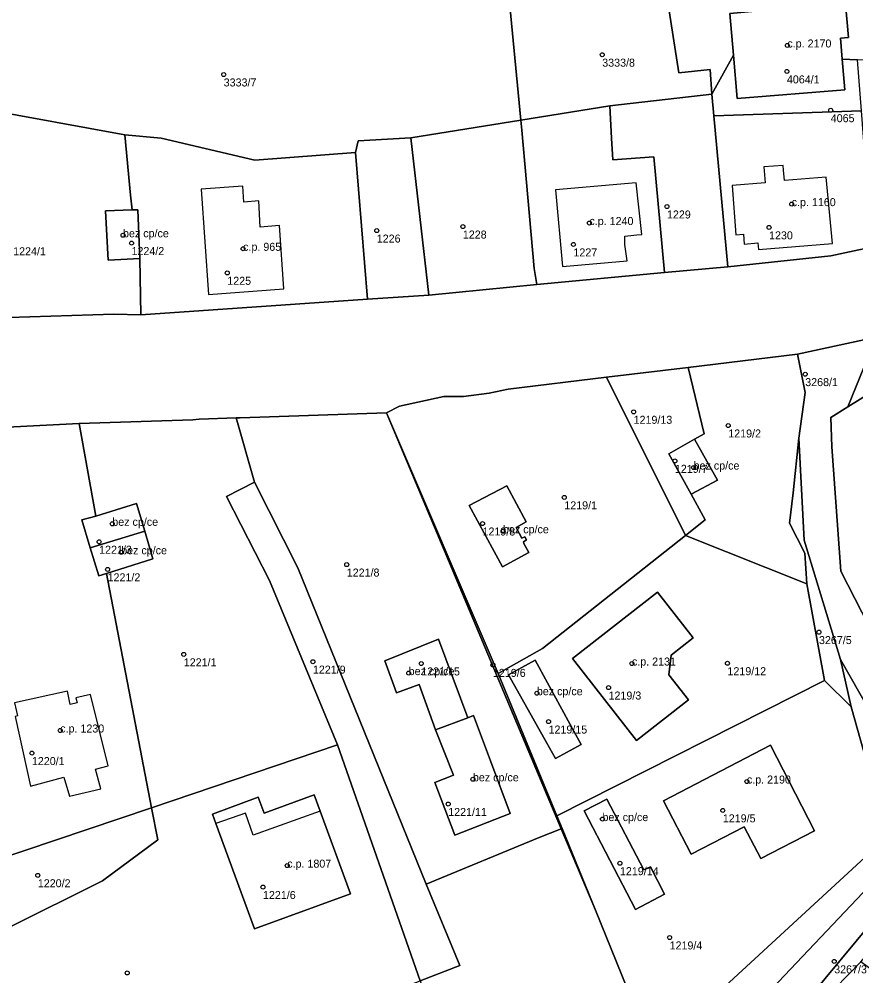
# Model space of a CAD drawing. Extents: x -878211 to -870363, y -1058464 to -1052522.
# Drawn here: x -875754.6 to -875650, y -1056338.1 to -1056218.5 of the extents above; entities that cross this region are included whole.
import ezdxf

# ---------------------------------------------------------------- set-up
doc = ezdxf.new("R2010")
doc.units = 0
for name, color, linetype in [('Vrstva 50', 7, 'Continuous'), ('Vrstva 51', 7, 'Continuous'), ('Vrstva 52', 7, 'Continuous')]:
    doc.layers.add(name, color=color, linetype=linetype)

msp = doc.modelspace()

# ---------------------------------------------------------------- linework, layer by layer
at = {"layer": 'Vrstva 50'}
for centre in [(-875658.59, -1056221.79994), (-875681.73, -1056222.95994), (-875729.04, -1056225.42994), (-875658.65, -1056225.04994), (-875653.17, -1056229.89994), (-875658.05, -1056241.62994), (-875673.64, -1056241.92994), (-875683.33, -1056243.98994), (-875709.91, -1056244.93994), (-875699.15, -1056244.43994), (-875660.88, -1056244.53994), (-875741.62, -1056245.51994), (-875740.56, -1056246.49994), (-875726.61, -1056247.20994), (-875685.33, -1056246.66994), (-875728.59, -1056250.21994), (-875656.36, -1056262.87994), (-875677.81, -1056267.58994), (-875665.98, -1056269.29994), (-875672.65, -1056273.71994), (-875670.31, -1056274.54994), (-875686.47, -1056278.27994), (-875742.96, -1056281.57994), (-875696.69, -1056281.54994), (-875694.13, -1056282.50994), (-875744.61, -1056283.82994), (-875741.85, -1056285.13994), (-875713.66, -1056286.67994), (-875743.55, -1056287.27994), (-875654.64, -1056295.11994), (-875734.03, -1056297.89994), (-875717.89, -1056298.80994), (-875666.08, -1056299.00994), (-875704.35, -1056299.03994), (-875695.39, -1056299.21994), (-875678.02, -1056299.03994), (-875705.92, -1056300.23994), (-875680.94, -1056302.04994), (-875689.9, -1056302.74994), (-875688.44, -1056306.29994), (-875749.47, -1056307.40994), (-875753.01, -1056310.23994), (-875697.89, -1056313.50994), (-875663.65, -1056313.78994), (-875700.98, -1056316.59994), (-875666.66, -1056317.39994), (-875681.7, -1056318.47994), (-875679.52, -1056323.99994), (-875721.1, -1056324.29994), (-875752.27, -1056325.50994), (-875724.13, -1056326.97994), (-875673.31, -1056333.27994), (-875652.74, -1056336.26994), (-875741.1, -1056337.70994)]:
    msp.add_circle(centre, 0.25, dxfattribs=at)
at = {"layer": 'Vrstva 51'}
for points in [[(-875725.16, -1056236.15), (-875712.56, -1056235.19), (-875712.23, -1056233.71), (-875705.64, -1056233.36), (-875691.89, -1056231.13), (-875693.69, -1056212.47), (-875696.36, -1056212.7), (-875722.48, -1056215.76), (-875734.27, -1056214.88), (-875746.69, -1056208.31), (-875753.19, -1056192.84), (-875758.13, -1056177.67), (-875755.87, -1056195.65), (-875753.15, -1056204.3), (-875763.53, -1056214.45), (-875759.23, -1056229.71), (-875741.39, -1056232.96), (-875736.87, -1056233.37)], [(-875691.89, -1056231.13), (-875680.79, -1056229.33), (-875668.04, -1056227.87), (-875668.25, -1056224.81), (-875672.16, -1056225.23), (-875674.08, -1056212.9), (-875665.21, -1056213.09), (-875654.49, -1056214.36), (-875647.13, -1056215.85), (-875654.87, -1056210.56), (-875687.08, -1056211.89), (-875693.69, -1056212.47)], [(-875665.21, -1056213.09), (-875674.08, -1056212.9), (-875672.16, -1056225.23), (-875668.25, -1056224.81), (-875668.04, -1056227.87), (-875665.34, -1056222.99), (-875665.77, -1056217.8), (-875660.26, -1056217.32), (-875660.37, -1056216.1), (-875654.42, -1056215.61), (-875654.32, -1056216.83), (-875651.32, -1056216.58), (-875650.95, -1056220.79), (-875651.94, -1056220.88), (-875651.73, -1056223.53), (-875649.81, -1056223.61), (-875636.91, -1056223.14), (-875647.13, -1056215.85), (-875654.49, -1056214.36)], [(-875665.34, -1056222.99), (-875664.88, -1056228.42), (-875651.43, -1056227.33), (-875651.73, -1056223.53), (-875651.94, -1056220.88), (-875650.95, -1056220.79), (-875651.32, -1056216.58), (-875654.32, -1056216.83), (-875654.42, -1056215.61), (-875660.37, -1056216.1), (-875660.26, -1056217.32), (-875665.77, -1056217.8)], [(-875665.34, -1056222.99), (-875668.04, -1056227.87), (-875667.79, -1056230.61), (-875649.32, -1056229.95), (-875649.81, -1056223.61), (-875651.73, -1056223.53), (-875651.43, -1056227.33), (-875664.88, -1056228.42)], [(-875668.04, -1056227.87), (-875680.79, -1056229.33), (-875680.56, -1056233.39), (-875680.41, -1056236.11), (-875675.27, -1056235.7), (-875673.94, -1056250.18), (-875666.04, -1056249.45), (-875667.79, -1056230.61)], [(-875680.79, -1056229.33), (-875691.89, -1056231.13), (-875691.78, -1056232.37), (-875690.23, -1056249.66), (-875689.91, -1056251.66), (-875673.94, -1056250.18), (-875675.27, -1056235.7), (-875680.41, -1056236.11), (-875680.56, -1056233.39)], [(-875741.39, -1056232.96), (-875759.23, -1056229.71), (-875758.54, -1056255.86), (-875742.77, -1056255.38), (-875739.4, -1056255.45), (-875739.51, -1056248.42), (-875743.48, -1056248.63), (-875743.8, -1056242.47), (-875740.49, -1056242.35), (-875740.67, -1056240.5)], [(-875645.38, -1056246.43), (-875646.3, -1056237.25), (-875647.81, -1056237.69), (-875648.81, -1056236.55), (-875649.32, -1056229.95), (-875667.79, -1056230.61), (-875666.04, -1056249.45), (-875653.18, -1056248.09)], [(-875691.89, -1056231.13), (-875705.64, -1056233.36), (-875703.39, -1056253.02), (-875689.91, -1056251.66), (-875690.23, -1056249.66), (-875691.78, -1056232.37)], [(-875739.51, -1056248.42), (-875739.4, -1056255.45), (-875711.05, -1056253.52), (-875712.56, -1056235.19), (-875725.16, -1056236.15), (-875736.87, -1056233.37), (-875741.39, -1056232.96), (-875740.67, -1056240.5), (-875740.49, -1056242.35), (-875739.77, -1056242.32)], [(-875712.56, -1056235.19), (-875711.05, -1056253.52), (-875703.39, -1056253.02), (-875705.64, -1056233.36), (-875712.23, -1056233.71)], [(-875739.51, -1056248.42), (-875739.77, -1056242.32), (-875740.49, -1056242.35), (-875743.8, -1056242.47), (-875743.48, -1056248.63)], [(-875647.49, -1056258.27), (-875651.02, -1056266.97), (-875633.44, -1056256.06), (-875633.64, -1056255.3)], [(-875633.44, -1056256.06), (-875651.02, -1056266.97), (-875653.18, -1056268.31), (-875653.03, -1056271.94), (-875651.92, -1056287.51), (-875643.13, -1056304.67), (-875633.03, -1056304.67), (-875621.48, -1056302.6), (-875626.03, -1056285.45), (-875627.65, -1056278.13)], [(-875657.32, -1056260.37), (-875670.99, -1056262.03), (-875669, -1056270.33), (-875670.18, -1056271.02), (-875667.34, -1056276.11), (-875670.61, -1056277.89), (-875668.86, -1056281.08), (-875671.33, -1056283.03), (-875656.16, -1056289.1), (-875656.42, -1056285.26), (-875658.32, -1056281.49), (-875657.87, -1056277.71), (-875657.17, -1056270.86), (-875656.36, -1056265.18)], [(-875681.21, -1056263.26), (-875671.33, -1056283.03), (-875668.86, -1056281.08), (-875670.61, -1056277.89), (-875673.39, -1056272.84), (-875670.18, -1056271.02), (-875669, -1056270.33), (-875670.99, -1056262.03)], [(-875681.21, -1056263.26), (-875693.47, -1056264.74), (-875695.88, -1056265.24), (-875699.05, -1056265.68), (-875701.53, -1056265.67), (-875707.05, -1056266.86), (-875708.7, -1056267.72), (-875694.72, -1056300.28), (-875689.19, -1056297.18), (-875671.33, -1056283.03)], [(-875732.09, -1056268.5), (-875732.89, -1056268.59), (-875747.11, -1056269.04), (-875745.02, -1056280.63), (-875739.93, -1056279.05), (-875738.91, -1056282.5), (-875737.88, -1056285.94), (-875743.68, -1056287.79), (-875738.05, -1056317.07), (-875714.83, -1056309.2), (-875723.33, -1056288.66), (-875728.69, -1056278.17), (-875725.2, -1056276.37), (-875727.49, -1056268.34)], [(-875686.86, -1056319.7), (-875708.7, -1056267.72), (-875726.98, -1056268.32), (-875727.49, -1056268.34), (-875725.2, -1056276.37), (-875719.78, -1056287.09), (-875703.74, -1056326.61), (-875689.62, -1056320.79)], [(-875686.86, -1056319.7), (-875682.59, -1056329.88), (-875686.75, -1056319.66), (-875687.42, -1056318.06), (-875694.72, -1056300.28), (-875708.7, -1056267.72)], [(-875768.46, -1056271.25), (-875776.25, -1056272.71), (-875771.36, -1056309.08), (-875769.67, -1056318.12), (-875763.34, -1056337.52), (-875757.22, -1056335.33), (-875756.47, -1056331.18), (-875758.02, -1056323.76), (-875738.05, -1056317.07), (-875743.68, -1056287.79), (-875744.66, -1056288.1), (-875745.71, -1056284.6), (-875746.76, -1056281.09), (-875745.02, -1056280.63), (-875747.11, -1056269.04), (-875761.01, -1056269.76)], [(-875670.61, -1056277.89), (-875667.34, -1056276.11), (-875670.18, -1056271.02), (-875673.39, -1056272.84)], [(-875656.16, -1056289.1), (-875653.97, -1056301.14), (-875650.62, -1056304.44), (-875651.97, -1056298.54), (-875656.48, -1056283.62), (-875657.17, -1056270.86), (-875657.87, -1056277.71), (-875658.32, -1056281.49), (-875656.42, -1056285.26)], [(-875725.2, -1056276.37), (-875728.69, -1056278.17), (-875723.33, -1056288.66), (-875714.83, -1056309.2), (-875704.48, -1056338.69), (-875699.54, -1056336.78), (-875703.74, -1056326.61), (-875719.78, -1056287.09)], [(-875691.59, -1056283.84), (-875691.18, -1056283.6), (-875691.42, -1056283.21), (-875691.76, -1056283.39), (-875692.5, -1056282.03), (-875691.22, -1056281.32), (-875693.64, -1056276.82), (-875698.34, -1056279.3), (-875694.21, -1056286.96), (-875690.9, -1056285.18), (-875691.52, -1056284.02)], [(-875691.59, -1056283.84), (-875691.52, -1056284.02), (-875690.9, -1056285.18), (-875694.21, -1056286.96), (-875698.34, -1056279.3), (-875693.64, -1056276.82), (-875691.22, -1056281.32), (-875692.5, -1056282.03), (-875691.76, -1056283.39), (-875691.42, -1056283.21), (-875691.18, -1056283.6)], [(-875738.91, -1056282.5), (-875739.93, -1056279.05), (-875745.02, -1056280.63), (-875746.76, -1056281.09), (-875745.71, -1056284.6)], [(-875744.66, -1056288.1), (-875743.68, -1056287.79), (-875737.88, -1056285.94), (-875738.91, -1056282.5), (-875745.71, -1056284.6)], [(-875671.33, -1056283.03), (-875689.19, -1056297.18), (-875694.72, -1056300.28), (-875687.42, -1056318.06), (-875653.97, -1056301.14), (-875656.16, -1056289.1)], [(-875677.46, -1056308.66), (-875685.45, -1056298.43), (-875674.83, -1056290.13), (-875670.37, -1056295.84), (-875673.12, -1056297.99), (-875673.42, -1056300.45), (-875670.96, -1056303.59)], [(-875677.46, -1056308.66), (-875670.96, -1056303.59), (-875673.42, -1056300.45), (-875673.12, -1056297.99), (-875670.37, -1056295.84), (-875674.83, -1056290.13), (-875685.45, -1056298.43)], [(-875698.51, -1056305.81), (-875702.18, -1056296), (-875708.92, -1056298.71), (-875707.43, -1056302.7), (-875704.6, -1056301.64), (-875702.56, -1056307.33)], [(-875698.51, -1056305.81), (-875697.8, -1056305.54), (-875695.68, -1056311.19), (-875693.22, -1056317.77), (-875700.15, -1056320.48), (-875702.66, -1056313.91), (-875700.31, -1056313.01), (-875702.56, -1056307.33), (-875704.6, -1056301.64), (-875707.43, -1056302.7), (-875708.92, -1056298.71), (-875702.18, -1056296)], [(-875642.54, -1056321.47), (-875642.63, -1056314.95), (-875651.97, -1056298.54), (-875650.62, -1056304.44), (-875646.62, -1056318.65), (-875647.82, -1056322.26), (-875646.14, -1056324.55), (-875663.43, -1056342.76), (-875673.95, -1056351.87), (-875694.33, -1056369.52), (-875703.32, -1056374.74), (-875703.43, -1056377.18), (-875695.25, -1056372.67), (-875703.53, -1056381.51), (-875697.87, -1056377.14), (-875677.29, -1056358.5), (-875662.3, -1056346.67), (-875657.54, -1056342.8), (-875646.31, -1056329.33)], [(-875693.43, -1056300.46), (-875690.12, -1056298.6), (-875685.47, -1056307.11), (-875684.37, -1056309.14), (-875687.59, -1056310.9), (-875688.69, -1056308.91)], [(-875693.43, -1056300.46), (-875688.69, -1056308.91), (-875687.59, -1056310.9), (-875684.37, -1056309.14), (-875685.47, -1056307.11), (-875690.12, -1056298.6)], [(-875675.36, -1056347.63), (-875647.82, -1056322.26), (-875646.62, -1056318.65), (-875650.62, -1056304.44), (-875653.97, -1056301.14), (-875687.42, -1056318.06), (-875686.75, -1056319.66), (-875682.59, -1056329.88)], [(-875698.51, -1056305.81), (-875702.56, -1056307.33), (-875700.31, -1056313.01), (-875702.66, -1056313.91), (-875700.15, -1056320.48), (-875693.22, -1056317.77), (-875695.68, -1056311.19), (-875697.8, -1056305.54)], [(-875704.48, -1056338.69), (-875714.83, -1056309.2), (-875738.05, -1056317.07), (-875737.28, -1056321.06), (-875744.17, -1056326.18), (-875756.07, -1056332.11), (-875757.22, -1056335.33), (-875755.32, -1056341.37), (-875750.57, -1056356.47)], [(-875674.07, -1056316.18), (-875660.72, -1056309.23), (-875655.21, -1056319.96), (-875661.89, -1056323.4), (-875663.99, -1056319.43), (-875670.62, -1056322.88)], [(-875674.07, -1056316.18), (-875670.62, -1056322.88), (-875663.99, -1056319.43), (-875661.89, -1056323.4), (-875655.21, -1056319.96), (-875660.72, -1056309.23)], [(-875730.45, -1056317.85), (-875724.73, -1056315.72), (-875723.99, -1056317.75), (-875717.74, -1056315.44), (-875716.97, -1056317.51), (-875713.2, -1056327.82), (-875725.18, -1056332.19), (-875730.01, -1056319.05)], [(-875730.45, -1056317.85), (-875730.01, -1056319.05), (-875725.18, -1056332.19), (-875713.2, -1056327.82), (-875716.97, -1056317.51), (-875717.74, -1056315.44), (-875723.99, -1056317.75), (-875724.73, -1056315.72)], [(-875683.99, -1056317.45), (-875681.17, -1056315.98), (-875676.52, -1056324.84), (-875675.7, -1056324.44), (-875673.94, -1056327.85), (-875677.57, -1056329.76)], [(-875683.99, -1056317.45), (-875677.57, -1056329.76), (-875673.94, -1056327.85), (-875675.7, -1056324.44), (-875676.52, -1056324.84), (-875681.17, -1056315.98)], [(-875737.28, -1056321.06), (-875738.05, -1056317.07), (-875758.02, -1056323.76), (-875756.47, -1056331.18), (-875757.22, -1056335.33), (-875756.07, -1056332.11), (-875744.17, -1056326.18)], [(-875696.95, -1056363.01), (-875675.36, -1056347.63), (-875682.59, -1056329.88), (-875686.86, -1056319.7), (-875689.62, -1056320.79), (-875703.74, -1056326.61), (-875699.54, -1056336.78), (-875704.48, -1056338.69)], [(-875647.82, -1056322.26), (-875675.36, -1056347.63), (-875673.95, -1056351.87), (-875663.43, -1056342.76), (-875646.14, -1056324.55)], [(-875618.16, -1056359.39), (-875649.39, -1056336.33), (-875654.29, -1056341.32), (-875651.93, -1056342.98), (-875648.52, -1056339.09), (-875645.98, -1056341.31), (-875649.39, -1056345.2), (-875622.28, -1056364.78)]]:
    msp.add_lwpolyline(points, close=True, dxfattribs=at)
for points in [[(-875507, -1056214.58), (-875528.47, -1056219.85), (-875541.05, -1056223.17), (-875601.76, -1056239.12), (-875602.58, -1056239.02), (-875603.21, -1056238.75), (-875604.5, -1056237.83), (-875615.89, -1056240.16), (-875638.93, -1056245.15), (-875645.38, -1056246.43), (-875653.18, -1056248.09), (-875666.04, -1056249.45), (-875673.94, -1056250.18), (-875689.91, -1056251.66), (-875703.39, -1056253.02), (-875711.05, -1056253.52), (-875739.4, -1056255.45), (-875742.77, -1056255.38), (-875758.54, -1056255.86)], [(-875761.01, -1056269.76), (-875747.11, -1056269.04), (-875732.89, -1056268.59), (-875732.09, -1056268.5), (-875727.49, -1056268.34), (-875726.98, -1056268.32), (-875708.7, -1056267.72), (-875707.05, -1056266.86), (-875701.53, -1056265.67), (-875699.05, -1056265.68), (-875695.88, -1056265.24), (-875693.47, -1056264.74), (-875681.21, -1056263.26), (-875670.99, -1056262.03), (-875657.32, -1056260.37), (-875647.49, -1056258.27), (-875633.64, -1056255.3), (-875619.59, -1056251.97), (-875611.38, -1056250.03), (-875591.34, -1056245.14)], [(-875654.29, -1056341.32), (-875649.39, -1056336.33), (-875642.54, -1056328.24), (-875639.67, -1056321.63), (-875641.18, -1056313.35), (-875643.13, -1056304.67), (-875651.92, -1056287.51), (-875653.03, -1056271.94), (-875653.18, -1056268.31), (-875651.02, -1056266.97), (-875647.49, -1056258.27), (-875657.32, -1056260.37), (-875656.36, -1056265.18), (-875657.17, -1056270.86), (-875656.48, -1056283.62), (-875651.97, -1056298.54), (-875642.63, -1056314.95), (-875642.54, -1056321.47), (-875646.31, -1056329.33), (-875657.54, -1056342.8)]]:
    msp.add_lwpolyline(points, dxfattribs=at)
at = {"layer": 'Vrstva 52'}
for points in [[(-875665.77, -1056217.8), (-875665.34, -1056222.99), (-875664.88, -1056228.42), (-875651.43, -1056227.33), (-875651.73, -1056223.53), (-875651.94, -1056220.88), (-875650.95, -1056220.79), (-875651.32, -1056216.58), (-875654.32, -1056216.83), (-875654.42, -1056215.61), (-875660.37, -1056216.1), (-875660.26, -1056217.32)], [(-875661.37, -1056238.97), (-875665.5, -1056239.3), (-875665.04, -1056245.46), (-875664.08, -1056245.4), (-875663.97, -1056246.64), (-875662.27, -1056246.48), (-875662.21, -1056247.31), (-875652.97, -1056246.54), (-875653.76, -1056238.24), (-875658.96, -1056238.67), (-875659.06, -1056237.37), (-875659.1, -1056236.79), (-875661.53, -1056236.98)], [(-875687.55, -1056239.82), (-875686.68, -1056249.42), (-875678.61, -1056248.72), (-875678.9, -1056246.67), (-875678.92, -1056245.62), (-875677.41, -1056245.47), (-875676.77, -1056245.41), (-875677.47, -1056238.96)], [(-875726.65, -1056239.4), (-875731.85, -1056239.77), (-875730.93, -1056252.92), (-875721.51, -1056252.22), (-875722.06, -1056244.29), (-875724.49, -1056244.52), (-875724.66, -1056241.23), (-875726.54, -1056241.38)], [(-875740.49, -1056242.35), (-875743.8, -1056242.47), (-875743.48, -1056248.63), (-875739.51, -1056248.42), (-875739.77, -1056242.32)], [(-875670.18, -1056271.02), (-875673.39, -1056272.84), (-875670.61, -1056277.89), (-875667.34, -1056276.11)], [(-875691.76, -1056283.39), (-875692.5, -1056282.03), (-875691.22, -1056281.32), (-875693.64, -1056276.82), (-875698.34, -1056279.3), (-875694.21, -1056286.96), (-875690.9, -1056285.18), (-875691.52, -1056284.02), (-875691.59, -1056283.84), (-875691.18, -1056283.6), (-875691.42, -1056283.21)], [(-875745.02, -1056280.63), (-875746.76, -1056281.09), (-875745.71, -1056284.6), (-875738.91, -1056282.5), (-875739.93, -1056279.05)], [(-875745.71, -1056284.6), (-875744.66, -1056288.1), (-875743.68, -1056287.79), (-875737.88, -1056285.94), (-875738.91, -1056282.5)], [(-875674.83, -1056290.13), (-875685.45, -1056298.43), (-875677.46, -1056308.66), (-875670.96, -1056303.59), (-875673.42, -1056300.45), (-875673.12, -1056297.99), (-875670.37, -1056295.84)], [(-875702.18, -1056296), (-875708.92, -1056298.71), (-875707.43, -1056302.7), (-875704.6, -1056301.64), (-875702.56, -1056307.33), (-875698.51, -1056305.81)], [(-875687.59, -1056310.9), (-875684.37, -1056309.14), (-875685.47, -1056307.11), (-875690.12, -1056298.6), (-875693.43, -1056300.46), (-875688.69, -1056308.91)], [(-875744.41, -1056314.68), (-875745.06, -1056312.24), (-875743.49, -1056311.83), (-875745.68, -1056302.92), (-875747.52, -1056303.34), (-875747.35, -1056303.96), (-875748.21, -1056304.18), (-875748.54, -1056302.5), (-875755.17, -1056303.96), (-875754.81, -1056305.59), (-875755.11, -1056305.66), (-875753.19, -1056314.38), (-875749, -1056313.26), (-875748.33, -1056315.62)], [(-875695.68, -1056311.19), (-875697.8, -1056305.54), (-875698.51, -1056305.81), (-875702.56, -1056307.33), (-875700.31, -1056313.01), (-875702.66, -1056313.91), (-875700.15, -1056320.48), (-875693.22, -1056317.77)], [(-875660.72, -1056309.23), (-875674.07, -1056316.18), (-875670.62, -1056322.88), (-875663.99, -1056319.43), (-875661.89, -1056323.4), (-875655.21, -1056319.96)], [(-875683.99, -1056317.45), (-875677.57, -1056329.76), (-875673.94, -1056327.85), (-875675.7, -1056324.44), (-875676.52, -1056324.84), (-875681.17, -1056315.98)], [(-875725.18, -1056332.19), (-875713.2, -1056327.82), (-875716.97, -1056317.51), (-875725.34, -1056320.49), (-875726.33, -1056317.75), (-875730.01, -1056319.05)]]:
    msp.add_lwpolyline(points, close=True, dxfattribs=at)

# ---------------------------------------------------------------- texts
at = {"layer": 'Vrstva 50'}
for s, p in [('c.p. 2170', (-875658.59, -1056222.05)), ('3333/8', (-875681.73, -1056224.449)), ('4064/1', (-875658.65, -1056226.539)), ('3333/7', (-875729.04, -1056226.919)), ('4065', (-875653.17, -1056231.389)), ('c.p. 1160', (-875658.05, -1056241.879)), ('1229', (-875673.64, -1056243.419)), ('c.p. 1240', (-875683.33, -1056244.24)), ('bez cp/ce', (-875741.62, -1056245.77)), ('1228', (-875699.15, -1056245.929)), ('1226', (-875709.91, -1056246.429)), ('1230', (-875660.88, -1056246.029)), ('1224/1', (-875755.35, -1056248.019)), ('1224/2', (-875740.56, -1056247.989)), ('c.p. 965', (-875726.61, -1056247.46)), ('1227', (-875685.33, -1056248.159)), ('1225', (-875728.59, -1056251.709)), ('3268/1', (-875656.36, -1056264.369)), ('1219/13', (-875677.81, -1056269.079)), ('1219/2', (-875665.98, -1056270.789)), ('1219/7', (-875672.65, -1056275.209)), ('bez cp/ce', (-875670.31, -1056274.8)), ('1219/1', (-875686.47, -1056279.769)), ('bez cp/ce', (-875742.96, -1056281.83)), ('1219/8', (-875696.69, -1056283.039)), ('bez cp/ce', (-875694.13, -1056282.76)), ('1221/3', (-875744.61, -1056285.319)), ('bez cp/ce', (-875741.85, -1056285.389)), ('1221/2', (-875743.55, -1056288.769)), ('1221/8', (-875713.66, -1056288.169)), ('3267/5', (-875654.64, -1056296.609)), ('1221/1', (-875734.03, -1056299.389)), ('c.p. 2131', (-875678.02, -1056299.29)), ('1221/9', (-875717.89, -1056300.299)), ('bez cp/ce', (-875705.92, -1056300.49)), ('1221/15', (-875704.35, -1056300.529)), ('1219/6', (-875695.39, -1056300.709)), ('1219/12', (-875666.08, -1056300.499)), ('bez cp/ce', (-875689.9, -1056303)), ('1219/3', (-875680.94, -1056303.539)), ('c.p. 1230', (-875749.47, -1056307.659)), ('1219/15', (-875688.44, -1056307.789)), ('1220/1', (-875753.01, -1056311.729)), ('bez cp/ce', (-875697.89, -1056313.76)), ('c.p. 2190', (-875663.65, -1056314.04)), ('1221/11', (-875700.98, -1056318.089)), ('bez cp/ce', (-875681.7, -1056318.73)), ('1219/5', (-875666.66, -1056318.889)), ('c.p. 1807', (-875721.1, -1056324.55)), ('1219/14', (-875679.52, -1056325.489)), ('1220/2', (-875752.27, -1056326.999)), ('1221/6', (-875724.13, -1056328.469)), ('1219/4', (-875673.31, -1056334.769)), ('3267/3', (-875652.74, -1056337.759))]:
    msp.add_text(s, height=0.999996, dxfattribs=at).set_placement(p)

doc.saveas('drawing.dxf')
